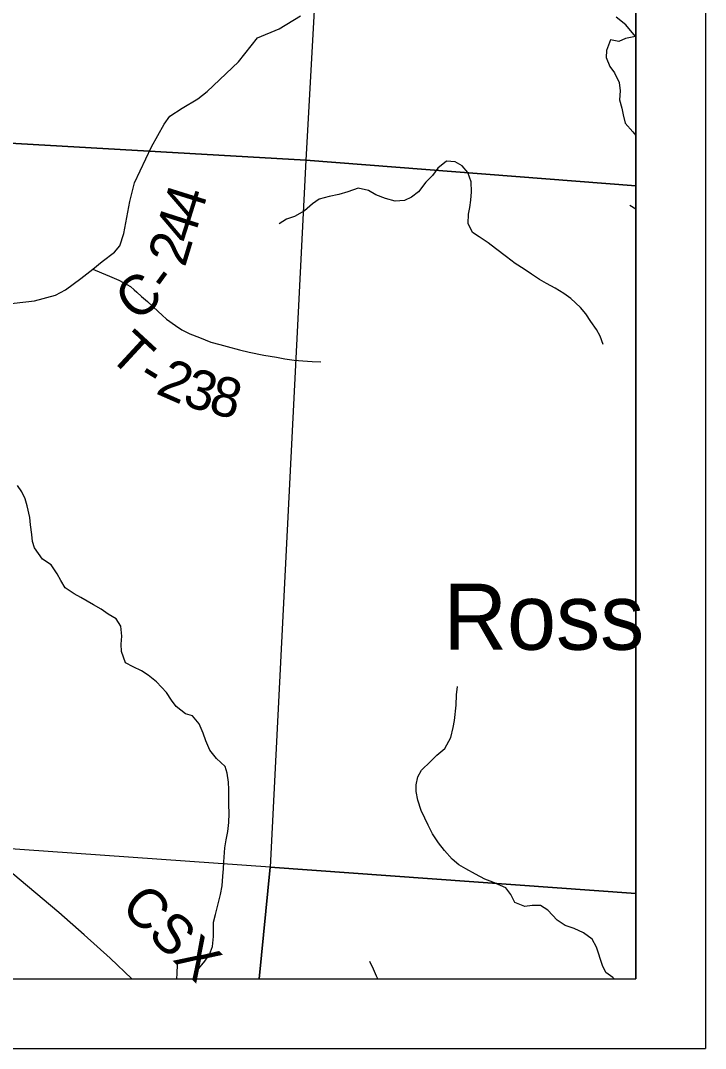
# Model space of a CAD drawing. Extents: x 0 to 34, y 0 to 22.
# Drawn here: x 8.016 to 9, y 14 to 15.475 of the extents above; entities that cross this region are included whole.
import ezdxf

# ---------------------------------------------------------------- set-up
doc = ezdxf.new("R2010")
doc.units = 0
for name, color, linetype in [('GM_X_Corporation', 7, 'Continuous'), ('GM_X_County_Road', 7, 'Continuous'), ('GM_X_County_Road_Text', 7, 'Continuous'), ('GM_X_Major_Lake', 7, 'Continuous'), ('GM_X_Major_Lake_Text', 7, 'Continuous'), ('GM_X_Minor_River', 7, 'Continuous'), ('GM_X_Rail_Line', 7, 'Continuous'), ('GM_X_Rail_Line_Text', 7, 'Continuous'), ('GM_X_Township_Road', 7, 'Continuous'), ('GM_X_Township_Road_Text', 7, 'Continuous'), ('SH_Data', 7, 'Continuous')]:
    doc.layers.add(name, color=color, linetype=linetype)

msp = doc.modelspace()

# ---------------------------------------------------------------- linework, layer by layer
at = {"layer": 'GM_X_Corporation'}
for p, q in [((8.9, 14.1), (8.9, 18.0235)), ((8.9, 15.0158), (8.9, 16.0103)), ((8.9, 14.1), (8.9, 15.0158)), ((7.1768, 14.1), (8.9, 14.1)), ((7.5024, 14.1), (8.3035, 14.1)), ((8.3035, 14.1), (8.9, 14.1))]:
    msp.add_line(p, q, dxfattribs=at)
msp.add_lwpolyline([(7.2283, 14.1), (8.9, 14.1), (8.9, 18.2459)], dxfattribs=at)
for points in [[(7.4964, 16.3324), (8.4813, 16.2644), (8.4262, 15.2749), (7.434, 15.3319)], [(8.9, 15.2382), (8.9, 16.2326), (8.4813, 16.2644), (8.4262, 15.2749)], [(7.434, 15.3319), (8.4262, 15.2749), (8.3747, 14.2604), (7.3773, 14.3307)], [(8.9, 14.2224), (8.9, 15.2382), (8.4262, 15.2749), (8.3747, 14.2604)], [(7.3832, 14.1), (8.3589, 14.1), (8.3747, 14.2604), (7.3773, 14.3307), (7.3654, 14.1329)], [(8.3589, 14.1), (8.9, 14.1), (8.9, 14.2224), (8.3747, 14.2604)]]:
    msp.add_lwpolyline(points, close=True, dxfattribs=at)
at = {"layer": 'GM_X_County_Road'}
for points in [[(8.1203, 15.1183), (8.1338, 15.1295), (8.1515, 15.1431), (8.1589, 15.1519), (8.1647, 15.1695), (8.1732, 15.2156), (8.18, 15.2426), (8.2046, 15.2939), (8.2224, 15.3268), (8.2309, 15.338), (8.2486, 15.3496), (8.2708, 15.3629), (8.2846, 15.3737), (8.3295, 15.4162), (8.3567, 15.4507), (8.388, 15.4633), (8.4184, 15.4821)], [(7.6745, 14.8605), (7.6746, 14.8614), (7.6791, 14.8687), (7.6873, 14.8757), (7.705, 14.8866), (7.7245, 14.9036), (7.7378, 14.9236), (7.7477, 14.9461), (7.7684, 14.9837), (7.7945, 15.0171), (7.8159, 15.0357), (7.8283, 15.0427), (7.9213, 15.0605), (7.9902, 15.068), (8.0364, 15.0729), (8.0666, 15.0814), (8.0809, 15.0888), (8.1031, 15.1051), (8.1203, 15.1183)]]:
    msp.add_lwpolyline(points, dxfattribs=at)
at = {"layer": 'GM_X_Major_Lake'}
msp.add_line((8.9, 15.2048), (8.8914, 15.21), dxfattribs=at)
for points in [[(8.9, 15.452), (8.8993, 15.4523), (8.8853, 15.4497), (8.8758, 15.4452), (8.8637, 15.4475), (8.8579, 15.4324), (8.8575, 15.4221), (8.8628, 15.4096)], [(8.8628, 15.4096), (8.8692, 15.4001), (8.8759, 15.3864), (8.8774, 15.3746), (8.8765, 15.3617), (8.8799, 15.3496), (8.8817, 15.3401), (8.8847, 15.3283), (8.8956, 15.3154), (8.9, 15.3106)]]:
    msp.add_lwpolyline(points, dxfattribs=at)
at = {"layer": 'GM_X_Minor_River'}
for p, q in [((8.2415, 14.1075), (8.2419, 14.1204)), ((8.5231, 14.1139), (8.5178, 14.1249)), ((8.2406, 14.1), (8.2415, 14.1075)), ((8.5276, 14.1036), (8.5231, 14.1139)), ((8.5295, 14.1), (8.5276, 14.1036))]:
    msp.add_line(p, q, dxfattribs=at)
for points in [[(8.8993, 15.4523), (8.8858, 15.4691), (8.8718, 15.4801)], [(8.8533, 15.0105), (8.8488, 15.0223), (8.8435, 15.0318), (8.8356, 15.0432), (8.8281, 15.0542), (8.8206, 15.0637), (8.8066, 15.0763), (8.7964, 15.0836), (8.7843, 15.0912), (8.7715, 15.0981), (8.7617, 15.1038), (8.75, 15.1111), (8.7398, 15.1183), (8.7266, 15.1267), (8.7145, 15.1362), (8.6986, 15.148), (8.6877, 15.1561), (8.6752, 15.1648), (8.6654, 15.1713), (8.6594, 15.1839), (8.6595, 15.1975), (8.6618, 15.207), (8.663, 15.2176), (8.6642, 15.2294), (8.6635, 15.2438), (8.6586, 15.2571), (8.6507, 15.2666), (8.6405, 15.2727), (8.628, 15.2735), (8.6155, 15.2637), (8.6082, 15.2531), (8.5983, 15.2433), (8.5877, 15.2297), (8.5778, 15.2217), (8.5679, 15.2172), (8.5543, 15.2161), (8.5403, 15.22), (8.5267, 15.2253), (8.5161, 15.2314), (8.5013, 15.2349), (8.4862, 15.2297), (8.4736, 15.2255), (8.4596, 15.2229), (8.4452, 15.2188), (8.4357, 15.2124), (8.4243, 15.2022), (8.4098, 15.1943), (8.3985, 15.1902), (8.3878, 15.1837)], [(8.2661, 14.1), (8.2698, 14.1119), (8.2811, 14.1252), (8.2876, 14.135), (8.2918, 14.1464), (8.2933, 14.1608), (8.2933, 14.1714), (8.2937, 14.1813), (8.2964, 14.1923), (8.2998, 14.2055), (8.3036, 14.221), (8.3059, 14.2332), (8.3071, 14.2472), (8.3079, 14.2578), (8.3083, 14.2677), (8.3098, 14.2877), (8.3117, 14.2995), (8.314, 14.3112), (8.3156, 14.3241), (8.316, 14.337), (8.3156, 14.3503), (8.3156, 14.3613), (8.3153, 14.3719), (8.3149, 14.3821), (8.313, 14.395), (8.3104, 14.4045), (8.298, 14.4162), (8.2881, 14.428), (8.2825, 14.4413), (8.2787, 14.4527), (8.2731, 14.4659), (8.2633, 14.4773), (8.2534, 14.4804), (8.2398, 14.4906), (8.233, 14.5001), (8.2258, 14.5107), (8.2115, 14.5263), (8.1998, 14.5358), (8.19, 14.5422), (8.1782, 14.5476), (8.1673, 14.5533), (8.1612, 14.5696), (8.1609, 14.5802), (8.1617, 14.5919), (8.1602, 14.606), (8.1538, 14.6166), (8.1424, 14.6234), (8.1322, 14.6303), (8.1213, 14.6367), (8.1031, 14.6474), (8.0933, 14.6527), (8.0804, 14.661), (8.074, 14.6717), (8.0687, 14.6812), (8.0604, 14.6941), (8.048, 14.7024), (8.0363, 14.7184), (8.0333, 14.7278), (8.0325, 14.7377), (8.0307, 14.7517), (8.0295, 14.762), (8.0258, 14.779), (8.0232, 14.7889), (8.0183, 14.7987), (8.0122, 14.8082)], [(8.6257, 14.4305), (8.6341, 14.4461), (8.6379, 14.4605), (8.6394, 14.4707), (8.6418, 14.4927), (8.6425, 14.5075), (8.6441, 14.5196)], [(8.8687, 14.1), (8.867, 14.1016), (8.8568, 14.1092), (8.8522, 14.119), (8.8436, 14.1452), (8.8375, 14.157), (8.8247, 14.1657), (8.8115, 14.1722), (8.7986, 14.1767), (8.7869, 14.1839), (8.7737, 14.1987), (8.7631, 14.2052), (8.7513, 14.2052), (8.7404, 14.2037), (8.726, 14.2094), (8.7203, 14.2208), (8.7135, 14.2303), (8.6946, 14.2387), (8.6833, 14.2432), (8.6697, 14.2501), (8.6557, 14.258), (8.6459, 14.2637), (8.636, 14.2717), (8.6251, 14.2839), (8.6168, 14.2949), (8.6081, 14.3078), (8.6017, 14.3203), (8.5972, 14.3305), (8.5919, 14.3415), (8.587, 14.3563), (8.5844, 14.3688), (8.5844, 14.3783), (8.5871, 14.3897), (8.592, 14.3995), (8.6049, 14.412), (8.6144, 14.4211), (8.6257, 14.4305)]]:
    msp.add_lwpolyline(points, dxfattribs=at)
at = {"layer": 'GM_X_Rail_Line'}
msp.add_lwpolyline([(8.1762, 14.1), (8.145, 14.1295), (8.1078, 14.1631), (8.0715, 14.1949), (7.9931, 14.2608), (7.8607, 14.3721), (7.7807, 14.4392), (7.5442, 14.6377), (7.4488, 14.7181), (7.3828, 14.7736), (7.3313, 14.8189), (7.278, 14.8689), (7.2388, 14.9081), (7.2061, 14.9425), (7.1705, 14.981), (7.1453, 15.0088), (7.0716, 15.0894), (6.9457, 15.2275)], dxfattribs=at)
at = {"layer": 'GM_X_Township_Road'}
msp.add_lwpolyline([(8.1203, 15.1183), (8.1325, 15.1133), (8.144, 15.1086), (8.1576, 15.1029), (8.1639, 15.0996), (8.1743, 15.0934), (8.1795, 15.0888), (8.1833, 15.0855), (8.1902, 15.0794), (8.1988, 15.0719), (8.2064, 15.0649), (8.2139, 15.0578), (8.2196, 15.0525), (8.2258, 15.0467), (8.2387, 15.0377), (8.2479, 15.0316), (8.2595, 15.0258), (8.2735, 15.0202), (8.2894, 15.0138), (8.3026, 15.0103), (8.3129, 15.0076), (8.3309, 15.0029), (8.3446, 14.9993), (8.3659, 14.995), (8.384, 14.992), (8.396, 14.99), (8.4092, 14.9879), (8.4217, 14.9868), (8.4351, 14.9862), (8.4474, 14.9857)], dxfattribs=at)
at = {"layer": 'SH_Data'}
for p, q in [((9, 21), (9, 14)), ((8.9, 20.9), (8.9, 14.1)), ((2.1, 14.1), (8.9, 14.1)), ((2, 14), (9, 14))]:
    msp.add_line(p, q, dxfattribs=at)

# ---------------------------------------------------------------- texts
at = {"layer": 'GM_X_County_Road_Text'}
for s, rotation, p in [('4', 72.6294, (8.2732, 15.1871)), ('4', 72.22, (8.2624, 15.1533)), ('2', 73.1011, (8.2523, 15.1201)), ('C', 39.056, (8.182, 15.0416)), ('-', 53.9079, (8.2293, 15.0827))]:
    msp.add_text(s, height=0.0568, rotation=rotation, dxfattribs=at).set_placement(p)
at = {"layer": 'GM_X_Major_Lake_Text'}
msp.add_text('Ross', height=0.09469, rotation=359.9948, dxfattribs=at).set_placement((8.6236, 14.5723))
at = {"layer": 'GM_X_Rail_Line_Text'}
msp.add_text('CSX', height=0.05663, rotation=315.7457, dxfattribs=at).set_placement((8.1582, 14.2004))
at = {"layer": 'GM_X_Township_Road_Text'}
for s, rotation, p in [('T', 317.2763, (8.1407, 14.993)), ('-', 328.4651, (8.1815, 14.9568)), ('2', 336.3108, (8.2089, 14.9407)), ('3', 342.4207, (8.2472, 14.9243)), ('8', 346.3018, (8.2846, 14.9126))]:
    msp.add_text(s, height=0.0568, rotation=rotation, dxfattribs=at).set_placement(p)

doc.saveas('drawing.dxf')
